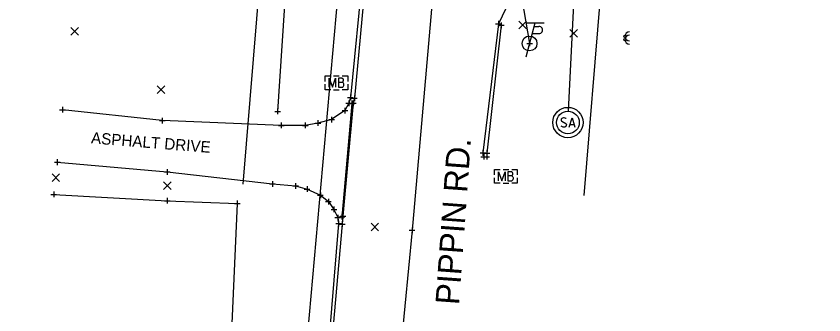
# Model space of a CAD drawing. Extents: x 1380550 to 1381945, y 468927 to 470496.
# Drawn here: x 1381450.4 to 1381592.6, y 469006.5 to 469059.1 of the extents above; entities that cross this region are included whole.
import ezdxf

# ---------------------------------------------------------------- set-up
doc = ezdxf.new("R2010")
doc.units = 0
for name, color, linetype in [('DR_X_Storm_Sewer', 7, 'Continuous'), ('GK_Drainage_Nodes', 7, 'Continuous'), ('PV_X_COP', 7, 'Continuous'), ('PV_X_Curb', 7, 'Continuous'), ('PV_X_Driveway', 7, 'Continuous'), ('PV_X_EOP', 7, 'Continuous'), ('RD_X_Cells', 7, 'Continuous'), ('RD_X_Fence', 7, 'Continuous'), ('RD_X_Text', 7, 'Continuous'), ('RW_X_Esmt_General', 7, 'Continuous'), ('SV_X_Random_Point', 7, 'Continuous'), ('SV_X_Shot_Marker', 7, 'Continuous'), ('SV_X_Toe_of_Slope', 7, 'Continuous'), ('UT_X_Electric', 7, 'Continuous'), ('UT_X_Misc_Cells', 7, 'Continuous'), ('UT_X_Sanitary_Cells', 7, 'Continuous'), ('UT_X_Telecom', 7, 'Continuous')]:
    doc.layers.add(name, color=color, linetype=linetype)

msp = doc.modelspace()

# ---------------------------------------------------------------- linework, layer by layer
at = {"layer": 'DR_X_Storm_Sewer'}
for p, q in [((1381528.04, 469296.45), (1381500.71, 468992.41)), ((1381547.66, 469042.33), (1381552.76, 469143.48))]:
    msp.add_line(p, q, dxfattribs=at)
at = {"layer": 'GK_Drainage_Nodes'}
for p, q in [((1381547.56, 469042.34), (1381547.56, 469042.34)), ((1381547.56, 469040.34), (1381547.56, 469040.34)), ((1381547.56, 469040.34), (1381547.56, 469040.34)), ((1381547.56, 469040.34), (1381547.56, 469040.34)), ((1381547.56, 469038.34), (1381547.56, 469038.34))]:
    msp.add_line(p, q, dxfattribs=at)
msp.add_circle((1381547.56, 469040.34), 2, dxfattribs=at)
at = {"layer": 'PV_X_COP'}
msp.add_lwpolyline([(1381585.99, 469815.58), (1381581.29, 469760.78), (1381580.3, 469747.86), (1381578.72, 469729.45), (1381576.78, 469708.95), (1381575.29, 469689.79), (1381572.76, 469657.56), (1381569.36, 469615.7), (1381565.36, 469567.23), (1381561.16, 469537.52), (1381558.94, 469486.81), (1381555.39, 469442.03), (1381550.97, 469391.02), (1381547.28, 469345.9), (1381541.95, 469289.55), (1381537.19, 469231.27), (1381533.05, 469168.09), (1381530.32, 469133.74), (1381523.97, 469065.08), (1381520.12, 469021.37), (1381518.18, 469001.31)], dxfattribs=at)
at = {"layer": 'PV_X_Curb'}
for points in [[(1381513.05, 469088.48), (1381513.17, 469087.56), (1381511.42, 469066.88), (1381509.25, 469044.75), (1381508.96, 469043.74)], [(1381535.81, 469057.46), (1381533.28, 469034.97), (1381533.26, 469034.32)], [(1381507.02, 469023.6), (1381507.17, 469022.55), (1381505.52, 469002.58)]]:
    msp.add_lwpolyline(points, dxfattribs=at)
at = {"layer": 'PV_X_Driveway'}
for points in [[(1381508.96, 469043.74), (1381508.3, 469042.45), (1381505.95, 469040.85), (1381503.53, 469040.25), (1381501.31, 469039.83), (1381497.09, 469039.83), (1381476.12, 469040.68), (1381458.55, 469042.58)], [(1381508.96, 469043.74), (1381509.51, 469043.7), (1381507.77, 469023.76), (1381507.02, 469023.6)], [(1381457.62, 469033.36), (1381476.99, 469031.64), (1381495.52, 469029.54), (1381499.59, 469029.19), (1381501.62, 469028.61), (1381503.96, 469027.52), (1381505.39, 469026.42), (1381506.34, 469025.03), (1381507.02, 469023.6)]]:
    msp.add_lwpolyline(points, dxfattribs=at)
at = {"layer": 'PV_X_EOP'}
for points in [[(1381521.19, 469168.77), (1381520.16, 469156.66), (1381518.94, 469140.36), (1381518.51, 469135.77), (1381515.95, 469110.14), (1381515.91, 469109.22), (1381513.99, 469088.5), (1381512.04, 469066.8), (1381509.95, 469044.61), (1381509.76, 469043.72), (1381507.94, 469023.87), (1381507.81, 469022.45), (1381506.02, 469002.56)], [(1381536.63, 469060.42), (1381535.33, 469057.72), (1381532.59, 469035), (1381532.73, 469034.31)]]:
    msp.add_lwpolyline(points, dxfattribs=at)
at = {"layer": 'RD_X_Cells'}
for p, q in [((1381506.3, 469048.56), (1381507.3, 469048.56)), ((1381506.81, 469047.34), (1381506.81, 469047.34)), ((1381506.3, 469046.12), (1381507.3, 469046.12)), ((1381536.14, 469032.09), (1381537.14, 469032.09)), ((1381536.65, 469030.87), (1381536.65, 469030.87)), ((1381536.14, 469029.64), (1381537.14, 469029.64))]:
    msp.add_line(p, q, dxfattribs=at)
for points in [[(1381504.81, 469047.59), (1381504.81, 469048.56), (1381505.78, 469048.56)], [(1381505.52, 469046.54), (1381505.52, 469048.14), (1381506.1, 469046.54), (1381506.65, 469048.14), (1381506.65, 469046.54)], [(1381507.83, 469047.41), (1381507.9, 469047.48), (1381507.94, 469047.51), (1381507.96, 469047.55), (1381507.97, 469047.58), (1381508, 469047.63), (1381508.01, 469047.66), (1381508.04, 469047.75), (1381508.04, 469047.79), (1381508.04, 469047.84), (1381508.02, 469047.92), (1381508, 469047.98), (1381507.96, 469048.03), (1381507.9, 469048.08), (1381507.85, 469048.11), (1381507.82, 469048.12), (1381507.76, 469048.14), (1381507.14, 469048.14), (1381507.14, 469046.54), (1381507.83, 469046.54), (1381507.92, 469046.59), (1381508, 469046.66), (1381508.06, 469046.76), (1381508.1, 469046.87), (1381508.11, 469046.98), (1381508.11, 469047.06), (1381508.09, 469047.14), (1381508.04, 469047.25), (1381507.97, 469047.32), (1381507.83, 469047.41), (1381507.14, 469047.41)], [(1381507.82, 469048.56), (1381508.81, 469048.56), (1381508.81, 469047.59)], [(1381505.78, 469046.12), (1381504.81, 469046.12), (1381504.81, 469047.09)], [(1381508.81, 469047.09), (1381508.81, 469046.12), (1381507.82, 469046.12)], [(1381534.65, 469031.12), (1381534.65, 469032.09), (1381535.62, 469032.09)], [(1381535.35, 469030.07), (1381535.35, 469031.67), (1381535.93, 469030.07), (1381536.49, 469031.67), (1381536.49, 469030.07)], [(1381537.67, 469030.94), (1381537.73, 469031), (1381537.77, 469031.04), (1381537.8, 469031.07), (1381537.81, 469031.1), (1381537.83, 469031.15), (1381537.85, 469031.19), (1381537.87, 469031.28), (1381537.87, 469031.31), (1381537.87, 469031.36), (1381537.86, 469031.44), (1381537.83, 469031.5), (1381537.8, 469031.55), (1381537.73, 469031.6), (1381537.68, 469031.63), (1381537.66, 469031.64), (1381537.6, 469031.67), (1381536.98, 469031.67), (1381536.98, 469030.07), (1381537.67, 469030.07), (1381537.76, 469030.12), (1381537.83, 469030.18), (1381537.9, 469030.28), (1381537.94, 469030.39), (1381537.95, 469030.51), (1381537.95, 469030.58), (1381537.92, 469030.66), (1381537.87, 469030.77), (1381537.81, 469030.85), (1381537.67, 469030.94), (1381536.98, 469030.94)], [(1381537.66, 469032.09), (1381538.65, 469032.09), (1381538.65, 469031.12)], [(1381535.62, 469029.64), (1381534.65, 469029.64), (1381534.65, 469030.61)], [(1381538.65, 469030.61), (1381538.65, 469029.64), (1381537.66, 469029.64)]]:
    msp.add_lwpolyline(points, dxfattribs=at)
at = {"layer": 'RD_X_Fence'}
msp.add_lwpolyline([(1381457.02, 469027.67), (1381476.99, 469026.56), (1381489.32, 469026.11), (1381488.25, 469002.32)], dxfattribs=at)
at = {"layer": 'RW_X_Esmt_General'}
msp.add_line((1381550.44, 469027.47), (1381557.61, 469114.29), dxfattribs=at)
msp.add_lwpolyline([(1381490.4, 469029.46), (1381590.2, 470237.18), (1380558.69, 470277.03)], dxfattribs=at)
at = {"layer": 'SV_X_Random_Point'}
for p, q in [((1381538.94, 469056.83), (1381540.28, 469058.17)), ((1381538.94, 469058.17), (1381540.28, 469056.83)), ((1381460.04, 469055.72), (1381461.37, 469057.05)), ((1381460.04, 469057.05), (1381461.37, 469055.72)), ((1381547.89, 469055.39), (1381549.22, 469056.72)), ((1381547.89, 469056.72), (1381549.22, 469055.39)), ((1381475.24, 469045.47), (1381476.57, 469046.8)), ((1381475.24, 469046.8), (1381476.57, 469045.47)), ((1381456.71, 469029.96), (1381458.04, 469031.3)), ((1381456.71, 469031.3), (1381458.04, 469029.96)), ((1381476.36, 469028.54), (1381477.7, 469029.87)), ((1381476.36, 469029.87), (1381477.7, 469028.54)), ((1381512.89, 469021.28), (1381514.22, 469022.62)), ((1381512.89, 469022.62), (1381514.22, 469021.28))]:
    msp.add_line(p, q, dxfattribs=at)
at = {"layer": 'SV_X_Shot_Marker'}
for p, q in [((1381535.33, 469058.22), (1381535.33, 469057.22)), ((1381535.81, 469057.96), (1381535.81, 469056.96)), ((1381534.83, 469057.72), (1381535.83, 469057.72)), ((1381535.31, 469057.46), (1381536.31, 469057.46)), ((1381535.33, 469057.72), (1381535.33, 469057.72)), ((1381535.81, 469057.46), (1381535.81, 469057.46)), ((1381540.3, 469054.26), (1381541.3, 469054.26)), ((1381540.3, 469054.26), (1381541.3, 469054.26)), ((1381540.3, 469054.26), (1381541.3, 469054.26)), ((1381540.8, 469054.76), (1381540.8, 469053.76)), ((1381540.8, 469054.76), (1381540.8, 469053.76)), ((1381540.8, 469054.76), (1381540.8, 469053.76)), ((1381540.8, 469054.26), (1381540.8, 469054.26)), ((1381540.8, 469054.26), (1381540.8, 469054.26)), ((1381540.8, 469054.26), (1381540.8, 469054.26)), ((1381509.25, 469045.25), (1381509.25, 469044.25)), ((1381509.95, 469045.11), (1381509.95, 469044.11)), ((1381508.46, 469043.74), (1381509.46, 469043.74)), ((1381508.46, 469043.74), (1381509.46, 469043.74)), ((1381508.46, 469043.74), (1381509.46, 469043.74)), ((1381508.75, 469044.75), (1381509.75, 469044.75)), ((1381508.96, 469044.24), (1381508.96, 469043.24)), ((1381508.96, 469044.24), (1381508.96, 469043.24)), ((1381508.96, 469044.24), (1381508.96, 469043.24)), ((1381508.96, 469043.74), (1381508.96, 469043.74)), ((1381508.96, 469043.74), (1381508.96, 469043.74)), ((1381508.96, 469043.74), (1381508.96, 469043.74)), ((1381509.01, 469043.7), (1381510.01, 469043.7)), ((1381509.25, 469044.75), (1381509.25, 469044.75)), ((1381509.26, 469043.72), (1381510.26, 469043.72)), ((1381509.45, 469044.61), (1381510.45, 469044.61)), ((1381509.51, 469044.2), (1381509.51, 469043.2)), ((1381509.51, 469043.7), (1381509.51, 469043.7)), ((1381509.76, 469044.22), (1381509.76, 469043.22)), ((1381509.76, 469043.72), (1381509.76, 469043.72)), ((1381509.95, 469044.61), (1381509.95, 469044.61)), ((1381458.05, 469042.58), (1381459.05, 469042.58)), ((1381458.55, 469043.08), (1381458.55, 469042.08)), ((1381458.55, 469042.58), (1381458.55, 469042.58)), ((1381495.93, 469042.3), (1381496.93, 469042.3)), ((1381496.43, 469042.8), (1381496.43, 469041.8)), ((1381496.43, 469042.3), (1381496.43, 469042.3)), ((1381507.8, 469042.45), (1381508.8, 469042.45)), ((1381508.3, 469042.95), (1381508.3, 469041.95)), ((1381508.3, 469042.45), (1381508.3, 469042.45)), ((1381475.62, 469040.68), (1381476.62, 469040.68)), ((1381476.12, 469041.18), (1381476.12, 469040.18)), ((1381476.12, 469040.68), (1381476.12, 469040.68)), ((1381503.53, 469040.75), (1381503.53, 469039.75)), ((1381505.45, 469040.85), (1381506.45, 469040.85)), ((1381505.95, 469041.35), (1381505.95, 469040.35)), ((1381505.95, 469040.85), (1381505.95, 469040.85)), ((1381496.59, 469039.83), (1381497.59, 469039.83)), ((1381497.09, 469040.33), (1381497.09, 469039.33)), ((1381497.09, 469039.83), (1381497.09, 469039.83)), ((1381500.81, 469039.83), (1381501.81, 469039.83)), ((1381501.31, 469040.33), (1381501.31, 469039.33)), ((1381501.31, 469039.83), (1381501.31, 469039.83)), ((1381503.03, 469040.25), (1381504.03, 469040.25)), ((1381503.53, 469040.25), (1381503.53, 469040.25)), ((1381532.09, 469035), (1381533.09, 469035)), ((1381532.59, 469035.5), (1381532.59, 469034.5)), ((1381532.59, 469035), (1381532.59, 469035)), ((1381532.78, 469034.97), (1381533.78, 469034.97)), ((1381533.28, 469035.47), (1381533.28, 469034.47)), ((1381533.28, 469034.97), (1381533.28, 469034.97)), ((1381457.62, 469033.86), (1381457.62, 469032.86)), ((1381532.23, 469034.31), (1381533.23, 469034.31)), ((1381532.73, 469034.81), (1381532.73, 469033.81)), ((1381532.73, 469034.31), (1381532.73, 469034.31)), ((1381532.76, 469034.32), (1381533.76, 469034.32)), ((1381533.26, 469034.82), (1381533.26, 469033.82)), ((1381533.26, 469034.32), (1381533.26, 469034.32)), ((1381457.12, 469033.36), (1381458.12, 469033.36)), ((1381457.62, 469033.36), (1381457.62, 469033.36)), ((1381476.99, 469032.14), (1381476.99, 469031.14)), ((1381476.49, 469031.64), (1381477.49, 469031.64)), ((1381476.99, 469031.64), (1381476.99, 469031.64)), ((1381495.02, 469029.54), (1381496.02, 469029.54)), ((1381495.52, 469030.04), (1381495.52, 469029.04)), ((1381495.52, 469029.54), (1381495.52, 469029.54)), ((1381499.59, 469029.69), (1381499.59, 469028.69)), ((1381457.02, 469028.17), (1381457.02, 469027.17)), ((1381499.09, 469029.19), (1381500.09, 469029.19)), ((1381499.59, 469029.19), (1381499.59, 469029.19)), ((1381501.12, 469028.61), (1381502.12, 469028.61)), ((1381501.62, 469029.11), (1381501.62, 469028.11)), ((1381501.62, 469028.61), (1381501.62, 469028.61)), ((1381503.96, 469028.02), (1381503.96, 469027.02)), ((1381456.52, 469027.67), (1381457.52, 469027.67)), ((1381457.02, 469027.67), (1381457.02, 469027.67)), ((1381476.49, 469026.56), (1381477.49, 469026.56)), ((1381476.99, 469027.06), (1381476.99, 469026.06)), ((1381476.99, 469026.56), (1381476.99, 469026.56)), ((1381489.32, 469026.61), (1381489.32, 469025.61)), ((1381503.46, 469027.52), (1381504.46, 469027.52)), ((1381503.96, 469027.52), (1381503.96, 469027.52)), ((1381505.39, 469026.92), (1381505.39, 469025.92)), ((1381488.82, 469026.11), (1381489.82, 469026.11)), ((1381489.32, 469026.11), (1381489.32, 469026.11)), ((1381504.89, 469026.42), (1381505.89, 469026.42)), ((1381505.39, 469026.42), (1381505.39, 469026.42)), ((1381505.84, 469025.03), (1381506.84, 469025.03)), ((1381506.34, 469025.53), (1381506.34, 469024.53)), ((1381506.34, 469025.03), (1381506.34, 469025.03)), ((1381506.52, 469023.6), (1381507.52, 469023.6)), ((1381506.52, 469023.6), (1381507.52, 469023.6)), ((1381506.52, 469023.6), (1381507.52, 469023.6)), ((1381507.02, 469024.1), (1381507.02, 469023.1)), ((1381507.02, 469024.1), (1381507.02, 469023.1)), ((1381507.02, 469024.1), (1381507.02, 469023.1)), ((1381507.02, 469023.6), (1381507.02, 469023.6)), ((1381507.02, 469023.6), (1381507.02, 469023.6)), ((1381507.02, 469023.6), (1381507.02, 469023.6)), ((1381507.27, 469023.76), (1381508.27, 469023.76)), ((1381507.44, 469023.87), (1381508.44, 469023.87)), ((1381507.77, 469024.26), (1381507.77, 469023.26)), ((1381507.77, 469023.76), (1381507.77, 469023.76)), ((1381507.94, 469024.37), (1381507.94, 469023.37)), ((1381507.94, 469023.87), (1381507.94, 469023.87)), ((1381506.67, 469022.55), (1381507.67, 469022.55)), ((1381507.17, 469023.05), (1381507.17, 469022.05)), ((1381507.17, 469022.55), (1381507.17, 469022.55)), ((1381507.31, 469022.45), (1381508.31, 469022.45)), ((1381507.81, 469022.95), (1381507.81, 469021.95)), ((1381507.81, 469022.45), (1381507.81, 469022.45)), ((1381519.62, 469021.37), (1381520.62, 469021.37)), ((1381520.12, 469021.87), (1381520.12, 469020.87)), ((1381520.12, 469021.37), (1381520.12, 469021.37))]:
    msp.add_line(p, q, dxfattribs=at)
at = {"layer": 'SV_X_Toe_of_Slope'}
msp.add_lwpolyline([(1381500.59, 469089.56), (1381498.03, 469066.37), (1381496.43, 469042.3)], dxfattribs=at)
at = {"layer": 'UT_X_Electric'}
msp.add_lwpolyline([(1381665.56, 470247.4), (1381595.79, 470220.83), (1381581.26, 470018.2), (1381571.97, 469887.64), (1381559.77, 469757.41), (1381543.86, 469565.78), (1381529.17, 469390.12), (1381515.28, 469203.1), (1381540.8, 469054.26)], dxfattribs=at)
at = {"layer": 'UT_X_Misc_Cells'}
for p, q in [((1381543.36, 469057.86), (1381540.16, 469057.86)), ((1381541.76, 469057.86), (1381540.16, 469051.86)), ((1381541.6, 469057.26), (1381542.45, 469057.26)), ((1381541.26, 469055.99), (1381542.45, 469055.99))]:
    msp.add_line(p, q, dxfattribs=at)
for centre, radius in [((1381540.8, 469054.26), 1.3), ((1381557.61, 469055.52), 0.2), ((1381557.61, 469054.91), 0.2)]:
    msp.add_circle(centre, radius, dxfattribs=at)
for centre, radius, start, end in [((1381542.47, 469056.63), 0.638, 268.8767, 91.1233), ((1381558.41, 469055.52), 0.8, 90, 270), ((1381558.41, 469054.91), 0.8, 90, 270)]:
    msp.add_arc(centre, radius, start, end, dxfattribs=at)
at = {"layer": 'UT_X_Sanitary_Cells'}
for points in [[(1381547.23, 469041.02), (1381547.21, 469041.05), (1381547.17, 469041.07), (1381547.06, 469041.11), (1381546.92, 469041.14), (1381546.82, 469041.14), (1381546.78, 469041.14), (1381546.61, 469041.1), (1381546.48, 469041.02), (1381546.39, 469040.92), (1381546.36, 469040.82), (1381546.36, 469040.74), (1381546.39, 469040.64), (1381546.49, 469040.56), (1381547.18, 469040.18), (1381547.24, 469040.13), (1381547.27, 469040.08), (1381547.29, 469040), (1381547.29, 469039.93), (1381547.28, 469039.85), (1381547.27, 469039.8), (1381547.24, 469039.74), (1381547.22, 469039.69), (1381547.19, 469039.65), (1381547.16, 469039.61), (1381547.12, 469039.59), (1381547.07, 469039.56), (1381547.03, 469039.55), (1381546.92, 469039.54), (1381546.74, 469039.54), (1381546.63, 469039.56), (1381546.46, 469039.65), (1381546.36, 469039.72)], [(1381547.77, 469039.54), (1381548.28, 469041.14), (1381548.77, 469039.54)], [(1381548.64, 469039.91), (1381547.9, 469039.91)]]:
    msp.add_lwpolyline(points, dxfattribs=at)
for radius in [2.67, 2]:
    msp.add_circle((1381547.56, 469040.34), radius, dxfattribs=at)
at = {"layer": 'UT_X_Telecom'}
msp.add_lwpolyline([(1381665.56, 470247.4), (1381595.35, 470217.51), (1381581.26, 470018.2), (1381571.97, 469887.64), (1381559.77, 469757.41), (1381543.86, 469565.78), (1381529.17, 469390.12), (1381515.28, 469203.1), (1381540.8, 469054.26)], dxfattribs=at)

# ---------------------------------------------------------------- texts
at = {"layer": 'RD_X_Text'}
for s, height, rotation, p in [('ASPHALT DRIVE', 2, 355.4428, (1381463.53, 469036.67)), ('PIPPIN RD.', 4.167, 85.8486, (1381528.38, 469008.14))]:
    msp.add_text(s, height=height, rotation=rotation, dxfattribs=at).set_placement(p)

doc.saveas('drawing.dxf')
